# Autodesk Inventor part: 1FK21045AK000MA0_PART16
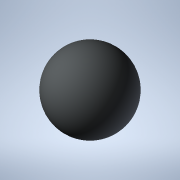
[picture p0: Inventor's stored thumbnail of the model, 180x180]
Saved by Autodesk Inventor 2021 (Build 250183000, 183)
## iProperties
Created: 2025-04
Part Number: 1FK21045AK000MA0_PART16
Material: Generic
Catalog Web Link: www.3dfindit.com
Description: -Servo synchronous motor
Document SubType Name: Modeling
Designer: psAdmin
Mass: 0.137258 g
Surface Area: 1.2868 cm^2
Volume: 0.137258 cm^3
Density: 1 g/cm^3
Appearance: PSOLRGB-212-217-219
Category: PARTsolutions
Title: 1FK21045AK000MA0_PART16
Author: Cadenas PARTsolutions
Comments: Servo synchronous motor
Sending System: PARTsolutions
Preprocessor: ST-DEVELOPER v19.3
PSOL_IDENT_0: {$CADENAS_DATA/23d-libs/siemens_ag/_cat_/3d/2f/1fk21045ak000ma0.prj},216 {VTYP=3D},{NB=1FK21045AK000
PSOL_IDENT_1: MA0_PART16},{LINA=1FK21045AK000MA0_PART16},{NN=1FK21045AK000MA0_PART16},{NOPRJ=TRUE},{DATE=19.08.202
PSOL_IDENT_2: 5 14:00:34},{GEOMDATE=30.07.2025 02:01:24},{VERSION=},{LINEID=10},{WBVAR=},{WBNUMERIC=}  {NB=1FK2104
PSOL_IDENT_3: 5AK000MA0_PART16},{LINA=1FK21045AK000MA0_PART16},{KT=DUMMY},{PREVIEW=../../../_pool_/a9/69/p_d211_xx
PSOL_IDENT_4: _00818j.png},{DESCSHORT=SIMOTICS S-1FK2 HD, SINAMICS S210 3AC 400V-480V, 1.7 Nm, 6000 rpm},{DESCLONG=
PSOL_IDENT_5: SIMOTICS S-1FK2 HD servo motor M0=2.4 Nm; PN = 1.07 kW at nN=6000 rpm (380-480 V); PN = 0.75 kW at n
PSOL_IDENT_6: N=3000 rpm (200-240 V); degree of protection IP64; cylindrical shaft D19x40mm; absolute encoder 22-b
PSOL_IDENT_7: it + 12-bit multiturn (encoder AM22DQC); with OCC interface; plug size M17, rotatable; SIMOTICS S-1F
PSOL_IDENT_8: K2 servomotorfor a wide range of uses in industrial environments. SIMOTICS S‑1FK2 servomotors are co
PSOL_IDENT_9: mpact synchronous motors with a high dynamic performance that set themselves apart as a result of th
PSOL_IDENT_10: eir high power density, degree of protection and overload capability. The motors are available in tw
PSOL_IDENT_11: o variants: as High Dynamic variant (highest dynamic performance as a result of the low intrinsic mo
PSOL_IDENT_12: ment of inertia for applications demanding a high dynamic performance with low moved masses) - and a
PSOL_IDENT_13: s Compact variant (precise and stable closed-loop control for medium up to large moved masses as a r
PSOL_IDENT_14: esult of a medium intrinsic moment of inertia). SIMOTICSS‑1FK2 servomotors fully exploit their stren
PSOL_IDENT_15: gths in a system with the SINAMICSS210 frequency converter and simple connection using the one cable
PSOL_IDENT_16: connection (OCC). Advantages include the short control and positioning times, fast and precise corr
PSOL_IDENT_17: ection of disturbing quantities as well as stable control with a high dynamic performance. The servo
PSOL_IDENT_18: motors can be configured to address a wide range of requirements. For example with and without hold
PSOL_IDENT_19: ing brake, IP64 or IP65 degree of protection, singleturn or multiturn absolute encoders - to name ju
PSOL_IDENT_20: st a few. Further, the servomotors are available in different shaft heights extending from 20 to 100
PSOL_IDENT_21: . A shaft sealing ring is available to achieve an IP65 degree of protection and for subsequent mount
PSOL_IDENT_22: ing at the motor or as spare part. SIMOTICS - the optimum motor for each and every motion control ap
PSOL_IDENT_23: plication.},{INTNO=804766789342},{SUPPLIERALTNO=1FK2104-5AK00-0MA0},{MANUID=1FK21045AK000MA0},{MANUN
PSOL_IDENT_24: AME=Siemens},{MANUTYPEDESC=Synchronous motor 1FK2-HD 2,39 Nm},{AAU732=SIMOTICS},{AAO057=S-1FK2},{AAU
PSOL_IDENT_25: 734=SIMOTICS S-1FK2 HD servo motor M0=2.4 Nm; PN = 1.07 kW at nN=6000 rpm (380-480 V); PN = 0.75 kW
PSOL_IDENT_26: at nN=3000 rpm (200-240 V); degree of protection IP64; cylindrical shaft D19x40mm; absolute encoder
PSOL_IDENT_27: 22-bit + 12-bit multiturn (encoder AM22DQC); with OCC interface; plug size M17, rotatable;},{AAW338=
PSOL_IDENT_28: Synchronous motor 1FK2-HD 2,39 Nm},{AAO742=SIMOTICS},{AAO663=4042948691151},{NOCUPEROU=1},{PRICEQUAN
PSOL_IDENT_29: TITY=1},{QUANTITYMIN=1},{QUANTITYINT=1},{CTN=85015100},{COO=DE},{AAO676=1FK2104-5AK00-0MA0},{AAO677=
PSOL_IDENT_30: Siemens AG},{ORDERUNIT=C62},{CONTENTUNIT=C62}
NB: 1FK21045AK000MA0_PART16
NT: Servo synchronous motor
NBSYN: $MANUID._PART16
LINA: 1FK21045AK000MA0_PART16
CATALOG: SIEMENS
PREVIEW: ../../../_pool_/a9/69/p_d211_xx_00818j.png
DESCSHORT: SIMOTICS S-1FK2 HD, SINAMICS S210 3AC 400V-480V, 1.7 Nm, 6000 rpm
DESCLONG: SIMOTICS S-1FK2 HD servo motor M0=2.4 Nm; PN = 1.07 kW at nN=6000 rpm (380-480 V); PN = 0.75 kW at nN=3000 rpm (200-240 V); degree of protection IP64; cylindric
INTNO: 804766789342
SUPPLIERALTNO: 1FK2104-5AK00-0MA0
MANUID: 1FK21045AK000MA0
MANUNAME: Siemens
MANUTYPEDESC: Synchronous motor 1FK2-HD 2,39 Nm
AAU732: SIMOTICS
AAO057: S-1FK2
AAU734: SIMOTICS S-1FK2 HD servo motor M0=2.4 Nm; PN = 1.07 kW at nN=6000 rpm (380-480 V); PN = 0.75 kW at nN=3000 rpm (200-240 V); degree of protection IP64; cylindric
AAW338: Synchronous motor 1FK2-HD 2,39 Nm
AAO742: SIMOTICS
AAO663: 4042948691151.0
NOCUPEROU: 1
PRICEQUANTITY: 1
QUANTITYMIN: 1
QUANTITYINT: 1
CTN: 85015100
COO: DE
ARTICLENO: 1FK21045AK000MA0_PART16
BOMINFO: 1FK21045AK000MA0_PART16
CREATOR: CADENAS GmbH
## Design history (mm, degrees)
feature "2025_04_17_15_39_51_0728"
body "Solid1"
